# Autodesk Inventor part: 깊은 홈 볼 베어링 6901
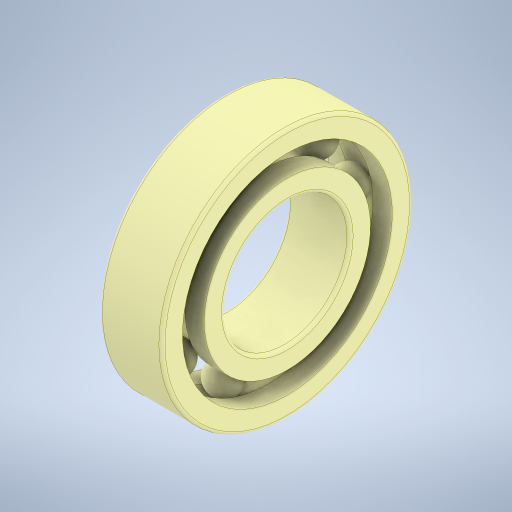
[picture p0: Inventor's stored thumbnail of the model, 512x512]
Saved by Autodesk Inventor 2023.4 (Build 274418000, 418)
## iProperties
Created: 2024-05
Part Number: 깊은 홈 볼 베어링 6901
Material: 강철, 연강
Description: 깊은 그루브 볼 베어링
Document SubType Name: Modeling
Designer: EDU-001
Density: 7.85 g/cm^3
Appearance: 기본값
Sending System: Autodesk Inventor 2025
Preprocessor: ST-DEVELOPER v20
Author: jhkim
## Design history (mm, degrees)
node "깊은 홈 볼 베어링 69011"
node "솔리드1"
node "솔리드2"
node "솔리드3"
node "솔리드4"
node "솔리드5"
node "솔리드6"
node "솔리드7"
node "솔리드8"
node "솔리드9"
node "솔리드10"
node "솔리드11"
body "Solid1"
node "Solid1:1"
node "Solid1:2"
node "Solid1:3"
node "Solid1:4"
node "Solid1:5"
node "Solid1:6"
node "Solid1:7"
node "Solid1:8"
node "Solid1:9"
node "Solid1:10"
